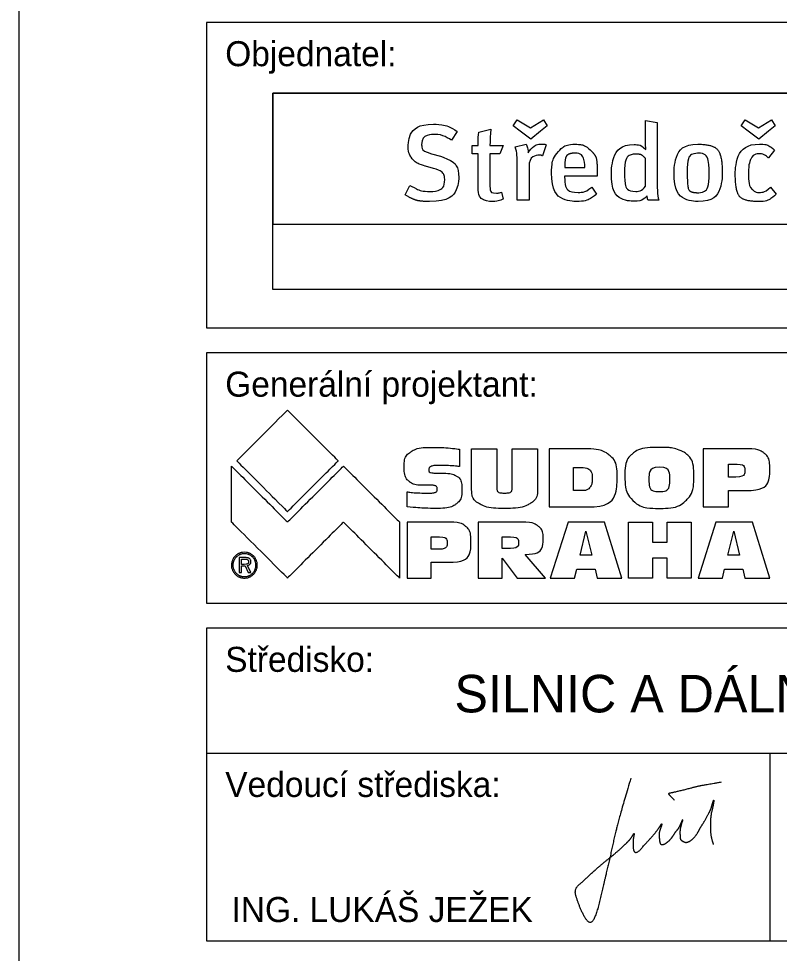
# Model space of a CAD drawing. Extents: x 2039 to 2249, y 760 to 1057.
# Drawn here: x 2038.7 to 2099.4, y 833.4 to 908.2 of the extents above; entities that cross this region are included whole.
import ezdxf

# ---------------------------------------------------------------- set-up
doc = ezdxf.new("R2010")
doc.units = 0
doc.layers.add('102_ZPEVNENI', color=7, linetype='Continuous')
doc.layers.add('120_ZPEVNENI', color=7, linetype='Continuous')

msp = doc.modelspace()

# ---------------------------------------------------------------- linework, layer by layer
at = {"layer": '102_ZPEVNENI'}
for points in [[(2083.73, 873.782), (2081.043, 873.782), (2081.043, 869.128), (2084.09, 869.128)], [(2096.82, 873.782), (2093.326, 873.782), (2093.326, 869.128), (2095.345, 869.128), (2095.345, 870.436), (2096.74, 870.436)], [(2083.563, 870.432), (2082.971, 870.432), (2082.971, 872.286), (2083.498, 872.286)], [(2095.943, 871.522), (2095.345, 871.522), (2095.345, 872.551), (2096.044, 872.551)], [(2073.025, 867.92), (2069.678, 867.92), (2069.678, 863.446), (2071.612, 863.446), (2071.612, 864.703), (2072.949, 864.703)], [(2078.766, 867.92), (2075.36, 867.92), (2075.36, 863.446), (2077.286, 863.446), (2077.286, 865.031), (2078.472, 863.446), (2080.73, 863.446), (2079.105, 865.333)], [(2083.063, 863.446), (2083.232, 864.143), (2084.695, 864.143), (2084.857, 863.446), (2086.838, 863.446), (2085.457, 867.92), (2082.546, 867.92), (2081.11, 863.446), (2083.063, 863.446)], [(2094.876, 863.446), (2095.045, 864.143), (2096.508, 864.143), (2096.67, 863.446), (2098.65, 863.446), (2097.27, 867.92), (2094.358, 867.92), (2092.923, 863.446), (2094.876, 863.446)], [(2072.185, 865.748), (2071.612, 865.748), (2071.612, 866.737), (2072.282, 866.737)], [(2077.929, 865.821), (2077.286, 865.821), (2077.286, 866.737), (2077.953, 866.737)], [(2083.97, 867.204), (2084.436, 865.28), (2083.498, 865.28), (2083.97, 867.204)], [(2095.783, 867.204), (2096.249, 865.28), (2095.31, 865.28), (2095.783, 867.204)], [(2056.709, 865.084), (2056.275, 865.084), (2056.275, 863.899), (2056.453, 863.899), (2056.453, 864.42), (2056.73, 864.42), (2056.98, 863.899), (2057.184, 863.899), (2056.92, 864.445)], [(2056.675, 864.538), (2056.453, 864.538), (2056.453, 864.963), (2056.675, 864.963)]]:
    msp.add_lwpolyline(points, dxfattribs=at)
for points in [[(2056.07, 872.814), (2056.07, 872.814), (2060.125, 876.869), (2060.125, 876.869), (2060.125, 876.869), (2060.125, 876.869), (2064.18, 872.814), (2064.18, 872.814), (2064.18, 872.814), (2064.18, 872.814), (2060.125, 868.759), (2060.125, 868.759), (2060.125, 868.759), (2060.125, 868.759), (2056.07, 872.814), (2056.07, 872.814)], [(2069.678, 869.147), (2070.405, 869.06), (2071.168, 869.016), (2071.968, 869.016), (2071.968, 869.016), (2072.733, 869.016), (2073.272, 869.129), (2073.584, 869.354), (2073.584, 869.354), (2073.899, 869.579), (2074.056, 869.967), (2074.056, 870.519), (2074.056, 870.519), (2074.056, 871.058), (2073.915, 871.418), (2073.631, 871.598), (2073.631, 871.598), (2073.365, 871.759), (2072.824, 871.84), (2072.007, 871.84), (2072.007, 871.84), (2071.616, 871.84), (2071.421, 871.932), (2071.421, 872.117), (2071.421, 872.117), (2071.421, 872.234), (2071.478, 872.319), (2071.593, 872.372), (2071.593, 872.372), (2071.711, 872.425), (2071.916, 872.451), (2072.209, 872.451), (2072.209, 872.451), (2072.706, 872.451), (2073.251, 872.423), (2073.87, 872.366), (2073.87, 872.366), (2073.87, 872.366), (2073.87, 873.738), (2073.87, 873.738), (2073.87, 873.738), (2073.131, 873.842), (2072.439, 873.894), (2071.77, 873.894), (2071.77, 873.894), (2070.927, 873.894), (2070.329, 873.774), (2069.977, 873.534), (2069.977, 873.534), (2069.624, 873.296), (2069.447, 872.916), (2069.447, 872.394), (2069.447, 872.394), (2069.447, 871.815), (2069.573, 871.413), (2069.825, 871.191), (2069.825, 871.191), (2070.08, 870.968), (2070.502, 870.858), (2071.093, 870.863), (2071.093, 870.863), (2071.093, 870.863), (2071.586, 870.863), (2071.586, 870.863), (2071.586, 870.863), (2071.759, 870.863), (2071.885, 870.844), (2071.964, 870.806), (2071.964, 870.806), (2072.043, 870.767), (2072.083, 870.684), (2072.083, 870.557), (2072.083, 870.557), (2072.083, 870.424), (2072.031, 870.337), (2071.928, 870.299), (2071.928, 870.299), (2071.827, 870.261), (2071.657, 870.242), (2071.417, 870.242), (2071.417, 870.242), (2070.673, 870.242), (2070.093, 870.275), (2069.678, 870.341), (2069.678, 870.341), (2069.678, 870.341), (2069.678, 869.147), (2069.678, 869.147)], [(2074.824, 870.617), (2074.824, 870.046), (2075.033, 869.635), (2075.452, 869.386), (2075.452, 869.386), (2075.871, 869.14), (2076.535, 869.016), (2077.444, 869.016), (2077.444, 869.016), (2078.391, 869.016), (2079.07, 869.14), (2079.482, 869.386), (2079.482, 869.386), (2079.896, 869.633), (2080.103, 870.05), (2080.103, 870.637), (2080.103, 870.637), (2080.103, 870.637), (2080.103, 873.782), (2080.103, 873.782), (2080.103, 873.782), (2080.103, 873.782), (2078.079, 873.782), (2078.079, 873.782), (2078.079, 873.782), (2078.079, 873.782), (2078.079, 870.7), (2078.079, 870.7), (2078.079, 870.7), (2078.079, 870.396), (2077.877, 870.244), (2077.472, 870.244), (2077.472, 870.244), (2077.056, 870.244), (2076.848, 870.401), (2076.848, 870.713), (2076.848, 870.713), (2076.848, 870.713), (2076.848, 873.782), (2076.848, 873.782), (2076.848, 873.782), (2076.848, 873.782), (2074.824, 873.782), (2074.824, 873.782), (2074.824, 873.782), (2074.824, 873.782), (2074.824, 870.617), (2074.824, 870.617)], [(2084.09, 869.128), (2085.668, 869.128), (2086.457, 869.952), (2086.457, 871.599), (2086.457, 871.599), (2086.457, 872.37), (2086.249, 872.926), (2085.833, 873.267), (2085.833, 873.267), (2085.416, 873.61), (2084.716, 873.782), (2083.73, 873.782)], [(2091.57, 873.62), (2091.154, 873.802), (2090.583, 873.894), (2089.855, 873.894), (2089.855, 873.894), (2088.836, 873.894), (2088.12, 873.726), (2087.705, 873.391), (2087.705, 873.391), (2087.291, 873.057), (2087.084, 872.463), (2087.084, 871.608), (2087.084, 871.608), (2087.084, 870.716), (2087.295, 870.061), (2087.716, 869.643)], [(2087.716, 869.643), (2088.138, 869.225), (2088.844, 869.016), (2089.834, 869.016), (2089.834, 869.016), (2090.785, 869.016), (2091.481, 869.217), (2091.922, 869.618), (2091.922, 869.618), (2092.365, 870.019), (2092.587, 870.682), (2092.587, 871.608), (2092.587, 871.608), (2092.587, 872.44), (2092.382, 873.029), (2091.973, 873.375), (2091.973, 873.375), (2091.861, 873.469), (2091.726, 873.551), (2091.57, 873.62)], [(2096.74, 870.436), (2098.013, 870.436), (2098.65, 871.006), (2098.65, 872.148), (2098.65, 872.148), (2098.65, 872.76), (2098.504, 873.185), (2098.212, 873.424), (2098.212, 873.424), (2097.922, 873.662), (2097.458, 873.782), (2096.82, 873.782)], [(2055.65, 867.92), (2055.65, 867.92), (2060.125, 863.446), (2060.125, 863.446), (2060.125, 863.446), (2060.125, 863.446), (2064.599, 867.92), (2064.599, 867.92), (2064.599, 867.92), (2064.599, 867.92), (2069.074, 863.446), (2069.074, 863.446), (2069.074, 863.446), (2069.074, 863.446), (2069.074, 867.92), (2069.074, 867.92), (2069.074, 867.92), (2069.074, 867.92), (2064.599, 872.395), (2064.599, 872.395), (2064.599, 872.395), (2064.599, 872.395), (2060.125, 867.92), (2060.125, 867.92), (2060.125, 867.92), (2060.125, 867.92), (2055.65, 872.395), (2055.65, 872.395), (2055.65, 872.395), (2055.65, 872.395), (2055.65, 867.92), (2055.65, 867.92)], [(2083.498, 872.286), (2083.892, 872.286), (2084.153, 872.22), (2084.279, 872.088), (2084.279, 872.088), (2084.404, 871.958), (2084.467, 871.736), (2084.467, 871.423), (2084.467, 871.423), (2084.467, 871.084), (2084.402, 870.834), (2084.271, 870.672), (2084.271, 870.672), (2084.143, 870.512), (2083.907, 870.432), (2083.563, 870.432)], [(2089.841, 872.308), (2090.392, 872.308), (2090.668, 871.999), (2090.668, 871.382), (2090.668, 871.382), (2090.668, 870.703), (2090.392, 870.363), (2089.841, 870.363), (2089.841, 870.363), (2089.282, 870.363), (2089.003, 870.687), (2089.003, 871.334), (2089.003, 871.334), (2089.003, 871.984), (2089.282, 872.308), (2089.841, 872.308)], [(2096.044, 872.551), (2096.457, 872.551), (2096.664, 872.383), (2096.664, 872.046), (2096.664, 872.046), (2096.664, 871.697), (2096.424, 871.522), (2095.943, 871.522)], [(2072.949, 864.703), (2074.169, 864.703), (2074.779, 865.252), (2074.779, 866.35), (2074.779, 866.35), (2074.779, 866.938), (2074.639, 867.347), (2074.359, 867.576), (2074.359, 867.576), (2074.081, 867.805), (2073.636, 867.92), (2073.025, 867.92)], [(2079.105, 865.333), (2080.068, 865.333), (2080.55, 865.754), (2080.55, 866.596), (2080.55, 866.596), (2080.55, 867.057), (2080.414, 867.393), (2080.142, 867.604), (2080.142, 867.604), (2079.87, 867.815), (2079.411, 867.92), (2078.766, 867.92)], [(2087.374, 863.446), (2087.374, 863.446), (2089.296, 863.446), (2089.296, 863.446), (2089.296, 863.446), (2089.296, 863.446), (2089.296, 865.028), (2089.296, 865.028), (2089.296, 865.028), (2089.296, 865.028), (2090.465, 865.028), (2090.465, 865.028), (2090.465, 865.028), (2090.465, 865.028), (2090.465, 863.446), (2090.465, 863.446), (2090.465, 863.446), (2090.465, 863.446), (2092.386, 863.446), (2092.386, 863.446), (2092.386, 863.446), (2092.386, 863.446), (2092.386, 867.92), (2092.386, 867.92), (2092.386, 867.92), (2092.386, 867.92), (2090.465, 867.92), (2090.465, 867.92), (2090.465, 867.92), (2090.465, 867.92), (2090.465, 866.328), (2090.465, 866.328), (2090.465, 866.328), (2090.465, 866.328), (2089.296, 866.328), (2089.296, 866.328), (2089.296, 866.328), (2089.296, 866.328), (2089.296, 867.92), (2089.296, 867.92), (2089.296, 867.92), (2089.296, 867.92), (2087.374, 867.92), (2087.374, 867.92), (2087.374, 867.92), (2087.374, 867.92), (2087.374, 863.446), (2087.374, 863.446)], [(2072.282, 866.737), (2072.678, 866.737), (2072.876, 866.575), (2072.876, 866.251), (2072.876, 866.251), (2072.876, 865.915), (2072.646, 865.748), (2072.185, 865.748)], [(2077.953, 866.737), (2078.38, 866.737), (2078.593, 866.597), (2078.593, 866.316), (2078.593, 866.316), (2078.593, 865.986), (2078.372, 865.821), (2077.929, 865.821)], [(2056.678, 865.504), (2056.539, 865.504), (2056.407, 865.479), (2056.284, 865.428), (2056.284, 865.428), (2056.161, 865.377), (2056.053, 865.304), (2055.958, 865.208), (2055.958, 865.208), (2055.859, 865.108), (2055.783, 864.994), (2055.73, 864.867), (2055.73, 864.867), (2055.677, 864.741), (2055.65, 864.61), (2055.65, 864.475), (2055.65, 864.475), (2055.65, 864.338), (2055.676, 864.208), (2055.728, 864.083), (2055.728, 864.083), (2055.779, 863.959), (2055.854, 863.848), (2055.953, 863.751), (2055.953, 863.751), (2056.05, 863.651), (2056.161, 863.576), (2056.285, 863.524), (2056.285, 863.524), (2056.342, 863.5), (2056.399, 863.482), (2056.458, 863.469)], [(2057.596, 864.471), (2057.596, 864.344), (2057.574, 864.227), (2057.53, 864.12), (2057.53, 864.12), (2057.485, 864.012), (2057.42, 863.916), (2057.335, 863.833), (2057.335, 863.833), (2057.244, 863.745), (2057.143, 863.678), (2057.03, 863.631), (2057.03, 863.631), (2056.917, 863.584), (2056.8, 863.561), (2056.678, 863.561), (2056.678, 863.561), (2056.557, 863.561), (2056.441, 863.584), (2056.331, 863.63), (2056.331, 863.63), (2056.22, 863.676), (2056.121, 863.743), (2056.033, 863.83), (2056.033, 863.83), (2055.945, 863.918), (2055.879, 864.017), (2055.832, 864.127), (2055.832, 864.127), (2055.786, 864.237), (2055.763, 864.353), (2055.763, 864.474), (2055.763, 864.474), (2055.763, 864.594), (2055.786, 864.71), (2055.834, 864.822), (2055.834, 864.822), (2055.881, 864.934), (2055.949, 865.035), (2056.038, 865.125), (2056.038, 865.125), (2056.124, 865.211), (2056.222, 865.277), (2056.331, 865.322), (2056.331, 865.322), (2056.441, 865.366), (2056.556, 865.389), (2056.678, 865.389), (2056.678, 865.389), (2056.803, 865.389), (2056.923, 865.366), (2057.034, 865.319), (2057.034, 865.319), (2057.147, 865.274), (2057.246, 865.207), (2057.335, 865.12), (2057.335, 865.12), (2057.419, 865.035), (2057.484, 864.937), (2057.529, 864.826), (2057.529, 864.826), (2057.574, 864.714), (2057.596, 864.596), (2057.596, 864.471)], [(2056.458, 863.469), (2056.529, 863.453), (2056.603, 863.446), (2056.678, 863.446), (2056.678, 863.446), (2056.814, 863.446), (2056.945, 863.472), (2057.072, 863.525), (2057.072, 863.525), (2057.199, 863.578), (2057.312, 863.654), (2057.412, 863.753), (2057.412, 863.753), (2057.509, 863.849), (2057.583, 863.958), (2057.633, 864.08), (2057.633, 864.08), (2057.684, 864.203), (2057.709, 864.335), (2057.709, 864.475), (2057.709, 864.475), (2057.709, 864.615), (2057.683, 864.747), (2057.632, 864.871), (2057.632, 864.871), (2057.581, 864.996), (2057.508, 865.107), (2057.412, 865.202), (2057.412, 865.202), (2057.315, 865.3), (2057.205, 865.375), (2057.079, 865.427), (2057.079, 865.427), (2056.954, 865.478), (2056.82, 865.504), (2056.678, 865.504)], [(2056.675, 864.963), (2056.795, 864.963), (2056.882, 864.946), (2056.935, 864.912), (2056.935, 864.912), (2056.988, 864.878), (2057.015, 864.822), (2057.015, 864.744), (2057.015, 864.744), (2057.015, 864.67), (2056.99, 864.616), (2056.939, 864.585), (2056.939, 864.585), (2056.889, 864.554), (2056.801, 864.538), (2056.675, 864.538)], [(2056.92, 864.445), (2057.005, 864.457), (2057.073, 864.491), (2057.124, 864.548), (2057.124, 864.548), (2057.174, 864.604), (2057.199, 864.673), (2057.199, 864.757), (2057.199, 864.757), (2057.199, 864.868), (2057.16, 864.951), (2057.079, 865.004), (2057.079, 865.004), (2056.999, 865.057), (2056.875, 865.084), (2056.709, 865.084)]]:
    msp.add_open_spline(points, degree=3, dxfattribs=at)
at = {"layer": '120_ZPEVNENI'}
for p, q in [((2233.65, 907.867), (2053.65, 907.867)), ((2053.65, 907.867), (2053.65, 883.446)), ((2073.671, 899.155), (2073.223, 898.456)), ((2075.405, 899.103), (2076.379, 899.336)), ((2078.317, 897.913), (2079.19, 898.136)), ((2080.802, 898.077), (2080.509, 897.196)), ((2099.032, 897.662), (2098.557, 897.032)), ((2071.635, 897.368), (2072.343, 897.161)), ((2088.727, 894.771), (2088.727, 896.99)), ((2071.799, 896.186), (2071.161, 896.367)), ((2082.273, 896.281), (2083.888, 896.281)), ((2069.522, 894.08), (2069.9, 894.84)), ((2084.429, 894.702), (2084.802, 894.124)), ((2098.704, 894.702), (2099.153, 894.124)), ((2077.234, 894.305), (2077.354, 893.735)), ((2089.804, 893.658), (2088.934, 893.658)), ((2053.65, 883.446), (2233.65, 883.446)), ((2053.65, 849.446), (2233.65, 849.446)), ((2098.65, 849.446), (2098.65, 834.446))]:
    msp.add_line(p, q, dxfattribs=at)
for points in [[(2038.65, 759.931), (2248.65, 759.931), (2248.65, 1056.931), (2038.65, 1056.931)], [(2058.95, 902.209), (2147.871, 902.209), (2147.871, 886.517), (2058.95, 886.517)], [(2053.65, 861.446), (2233.65, 861.446), (2233.65, 881.446), (2053.65, 881.446)], [(2053.65, 834.446), (2233.65, 834.446), (2233.65, 859.446), (2053.65, 859.446)]]:
    msp.add_lwpolyline(points, close=True, dxfattribs=at)
for points in [[(2137.41, 891.748), (2147.871, 902.209), (2058.95, 902.209), (2058.95, 891.748), (2137.41, 891.748)], [(2080.328, 899.163), (2079.553, 898.543), (2078.722, 899.172), (2078.152, 899.604), (2078.463, 900.069), (2079.541, 899.441), (2080.579, 900.069), (2080.862, 899.604), (2080.328, 899.163)], [(2088.727, 898.422), (2088.727, 900.019), (2089.666, 899.871), (2089.666, 895.176)], [(2098.548, 899.163), (2097.772, 898.543), (2096.942, 899.172), (2096.373, 899.604), (2096.684, 900.069), (2097.762, 899.441), (2098.798, 900.069), (2099.083, 899.604), (2098.548, 899.163)], [(2075.362, 894.667), (2075.362, 897.368), (2074.878, 897.368), (2074.878, 898.024), (2075.362, 898.024)], [(2076.303, 898.024), (2077.346, 898.024), (2077.096, 897.368), (2076.293, 897.368), (2076.293, 894.917)], [(2079.423, 896.609), (2079.423, 893.658), (2078.472, 893.658), (2078.472, 896.738)], [(2084.871, 895.781), (2084.871, 895.582), (2082.264, 895.582), (2082.264, 895.513)]]:
    msp.add_lwpolyline(points, dxfattribs=at)
for points, degree in [([(2069.754, 897.955), (2069.754, 897.955), (2069.754, 899.008), (2070.582, 899.725), (2071.782, 899.725)], 3), ([(2071.782, 899.725), (2071.782, 899.725), (2072.463, 899.725), (2073.145, 899.526), (2073.671, 899.155)], 3), ([(2071.818, 898.913), (2071.818, 898.913), (2071.23, 898.913), (2070.841, 898.594), (2070.841, 898.102)], 3), ([(2073.223, 898.456), (2073.223, 898.456), (2072.671, 898.785), (2072.292, 898.913), (2071.818, 898.913)], 3), ([(2075.362, 898.024), (2075.362, 898.024), (2075.362, 898.395), (2075.362, 898.776), (2075.405, 899.103)], 3), ([(2076.379, 899.336), (2076.379, 899.336), (2076.337, 898.983), (2076.303, 898.456), (2076.303, 898.024)], 3), ([(2079.19, 898.136), (2079.19, 898.136), (2079.292, 897.939), (2079.352, 897.688), (2079.352, 897.447)], 3), ([(2079.352, 897.447), (2079.352, 897.447), (2079.697, 897.921), (2080.043, 898.146), (2080.466, 898.146)], 3), ([(2080.466, 898.146), (2080.466, 898.146), (2080.604, 898.146), (2080.691, 898.129), (2080.802, 898.077)], 3), ([(2081.764, 897.542), (2081.764, 897.542), (2082.118, 897.947), (2082.55, 898.129), (2083.102, 898.129)], 3), ([(2083.102, 898.129), (2083.102, 898.129), (2083.533, 898.129), (2083.931, 898.016), (2084.302, 897.68)], 3), ([(2088.752, 897.705), (2088.752, 897.705), (2088.752, 897.705), (2088.727, 898.042), (2088.727, 898.422)], 3), ([(2091.005, 895.833), (2091.005, 895.833), (2091.005, 897.231), (2091.756, 898.129), (2092.913, 898.129)], 3), ([(2092.913, 898.129), (2094.156, 898.129), (2094.863, 897.205), (2094.863, 895.824)], 2), ([(2095.899, 895.788), (2095.899, 895.788), (2095.899, 897.376), (2096.848, 898.136), (2097.823, 898.136)], 3), ([(2097.823, 898.136), (2097.823, 898.136), (2098.297, 898.136), (2098.643, 898.024), (2099.032, 897.662)], 3), ([(2070.004, 897.084), (2070.004, 897.084), (2069.84, 897.325), (2069.754, 897.61), (2069.754, 897.955)], 3), ([(2070.841, 898.102), (2070.841, 898.102), (2070.841, 897.732), (2071.047, 897.542), (2071.635, 897.368)], 3), ([(2078.472, 896.738), (2078.472, 896.738), (2078.472, 897.291), (2078.413, 897.645), (2078.317, 897.913)], 3), ([(2081.221, 895.833), (2081.221, 895.833), (2081.221, 896.601), (2081.383, 897.11), (2081.764, 897.542)], 3), ([(2083.102, 897.412), (2082.569, 897.412), (2082.273, 896.99), (2082.273, 896.281)], 2), ([(2083.888, 896.281), (2083.888, 896.281), (2083.888, 896.99), (2083.576, 897.412), (2083.102, 897.412)], 3), ([(2084.302, 897.68), (2084.681, 897.334), (2084.871, 896.799), (2084.871, 895.781)], 2), ([(2085.999, 895.798), (2085.999, 895.798), (2085.999, 897.17), (2086.759, 898.102), (2087.811, 898.102)], 3), ([(2087.811, 898.102), (2087.811, 898.102), (2088.181, 898.102), (2088.484, 897.982), (2088.752, 897.705)], 3), ([(2092.921, 897.412), (2092.921, 897.412), (2092.318, 897.412), (2092.057, 896.954), (2092.057, 895.893)], 3), ([(2093.817, 895.806), (2093.817, 895.806), (2093.817, 897.041), (2093.473, 897.412), (2092.921, 897.412)], 3), ([(2071.161, 896.367), (2071.161, 896.367), (2070.617, 896.522), (2070.229, 896.747), (2070.004, 897.084)], 3), ([(2072.343, 897.161), (2072.343, 897.161), (2073.206, 896.911), (2073.809, 896.359), (2073.809, 895.461)], 3), ([(2080.241, 897.256), (2080.241, 897.256), (2079.844, 897.256), (2079.508, 896.963), (2079.423, 896.609)], 3), ([(2080.509, 897.196), (2080.415, 897.231), (2080.345, 897.256), (2080.241, 897.256)], 2), ([(2087.933, 897.342), (2087.933, 897.342), (2087.328, 897.342), (2087.05, 896.859), (2087.05, 895.806)], 3), ([(2088.727, 896.99), (2088.511, 897.222), (2088.251, 897.342), (2087.933, 897.342)], 2), ([(2097.133, 896.928), (2097.133, 896.928), (2097.002, 896.661), (2096.953, 896.255), (2096.953, 895.712)], 3), ([(2097.823, 897.368), (2097.823, 897.368), (2097.521, 897.368), (2097.27, 897.212), (2097.133, 896.928)], 3), ([(2098.557, 897.032), (2098.557, 897.032), (2098.297, 897.265), (2098.074, 897.368), (2097.823, 897.368)], 3), ([(2072.688, 895.297), (2072.688, 895.297), (2072.688, 895.738), (2072.411, 896.014), (2071.799, 896.186)], 3), ([(2092.057, 895.893), (2092.057, 894.624), (2092.378, 894.253), (2092.947, 894.253)], 2), ([(2073.809, 895.461), (2073.809, 895.461), (2073.809, 894.468), (2073.007, 893.546), (2071.48, 893.546)], 3), ([(2071.512, 894.348), (2071.512, 894.348), (2072.248, 894.348), (2072.688, 894.702), (2072.688, 895.297)], 3), ([(2083.232, 893.546), (2083.232, 893.546), (2081.997, 893.546), (2081.221, 894.434), (2081.221, 895.833)], 3), ([(2082.264, 895.513), (2082.264, 895.513), (2082.264, 894.909), (2082.49, 894.271), (2083.344, 894.271)], 3), ([(2087.786, 893.563), (2087.786, 893.563), (2086.672, 893.563), (2085.999, 894.434), (2085.999, 895.798)], 3), ([(2087.05, 895.806), (2087.05, 895.806), (2087.05, 894.84), (2087.242, 894.356), (2087.958, 894.356)], 3), ([(2089.666, 895.176), (2089.666, 895.176), (2089.666, 894.313), (2089.72, 893.873), (2089.804, 893.658)], 3), ([(2092.929, 893.546), (2092.929, 893.546), (2091.747, 893.546), (2091.005, 894.434), (2091.005, 895.833)], 3), ([(2094.863, 895.824), (2094.863, 895.824), (2094.863, 894.417), (2094.111, 893.546), (2092.929, 893.546)], 3), ([(2092.947, 894.253), (2092.947, 894.253), (2093.508, 894.253), (2093.817, 894.711), (2093.817, 895.806)], 3), ([(2097.755, 893.546), (2096.563, 893.546), (2095.899, 894.383), (2095.899, 895.788)], 2), ([(2096.953, 895.712), (2096.953, 895.712), (2096.953, 895.116), (2097.046, 894.737), (2097.245, 894.521)], 3), ([(2069.9, 894.84), (2069.9, 894.84), (2070.435, 894.529), (2070.91, 894.348), (2071.512, 894.348)], 3), ([(2076.501, 893.546), (2076.501, 893.546), (2075.655, 893.546), (2075.362, 894.047), (2075.362, 894.667)], 3), ([(2076.293, 894.917), (2076.293, 894.917), (2076.293, 894.374), (2076.414, 894.219), (2076.828, 894.219)], 3), ([(2083.344, 894.271), (2083.344, 894.271), (2083.748, 894.271), (2084.103, 894.417), (2084.429, 894.702)], 3), ([(2087.958, 894.356), (2087.958, 894.356), (2088.311, 894.356), (2088.598, 894.555), (2088.727, 894.771)], 3), ([(2097.245, 894.521), (2097.245, 894.521), (2097.383, 894.365), (2097.59, 894.271), (2097.823, 894.271)], 3), ([(2097.823, 894.271), (2097.823, 894.271), (2098.126, 894.271), (2098.42, 894.417), (2098.704, 894.702)], 3), ([(2071.48, 893.546), (2070.799, 893.546), (2070.108, 893.727), (2069.522, 894.08)], 2), ([(2077.354, 893.735), (2077.354, 893.735), (2077.069, 893.606), (2076.793, 893.546), (2076.501, 893.546)], 3), ([(2076.828, 894.219), (2076.828, 894.219), (2076.958, 894.219), (2077.069, 894.244), (2077.234, 894.305)], 3), ([(2084.802, 894.124), (2084.802, 894.124), (2084.345, 893.735), (2083.819, 893.546), (2083.232, 893.546)], 3), ([(2088.856, 893.994), (2088.856, 893.994), (2088.562, 893.702), (2088.217, 893.563), (2087.786, 893.563)], 3), ([(2088.934, 893.658), (2088.889, 893.752), (2088.882, 893.813), (2088.856, 893.994)], 2), ([(2099.153, 894.124), (2099.153, 894.124), (2098.754, 893.727), (2098.341, 893.546), (2097.755, 893.546)], 3), ([(2142.641, 886.517), (2142.641, 886.517), (2137.41, 891.748), (2137.41, 891.748), (2137.41, 891.748), (2137.41, 891.748), (2058.95, 891.748), (2058.95, 891.748), (2058.95, 891.748), (2058.95, 891.748), (2058.95, 886.517), (2058.95, 886.517), (2058.95, 886.517), (2058.95, 886.517), (2142.641, 886.517), (2142.641, 886.517)], 3), ([(2087.555, 847.436), (2087.126, 846.021), (2086.599, 844.163), (2086.297, 842.974), (2086.064, 841.93), (2085.808, 840.759), (2085.558, 839.73), (2085.324, 838.701), (2085.127, 837.846), (2084.849, 836.768), (2084.55, 836.032), (2084.264, 835.858), (2083.982, 836.138), (2083.666, 836.711), (2083.429, 837.274), (2083.24, 837.809), (2083.085, 838.299), (2083.212, 838.775), (2083.644, 839.113), (2084.131, 839.58), (2084.989, 840.366), (2086.193, 841.344), (2086.787, 841.849), (2087.2, 842.249), (2087.567, 842.63), (2087.863, 843.147), (2087.741, 842.594), (2087.724, 842.093), (2087.765, 841.69), (2087.903, 841.464), (2088.252, 841.626), (2088.483, 841.937), (2088.849, 842.334), (2089.376, 842.912), (2089.781, 843.436), (2090.08, 843.907), (2089.964, 843.51), (2089.842, 843.206), (2089.811, 842.954), (2089.839, 842.488), (2089.885, 842.241), (2089.97, 842.137), (2090.187, 842.15), (2090.399, 842.272), (2090.711, 842.525), (2090.97, 842.884), (2091.169, 843.209), (2091.384, 843.427), (2091.618, 843.948), (2091.732, 844.211), (2091.55, 843.645), (2091.478, 843.259), (2091.48, 842.962), (2091.5, 842.636), (2091.523, 842.512), (2091.977, 842.244), (2092.49, 842.54), (2092.881, 843.032), (2093.089, 843.466), (2093.432, 843.986), (2093.795, 844.68), (2093.95, 844.954), (2094.066, 845.367), (2094.209, 845.829), (2094.124, 845.184), (2093.93, 844.481), (2093.909, 843.579), (2093.91, 843.064), (2094.08, 842.309), (2094.153, 842.142)], 2), ([(2091.053, 845.673), (2090.653, 846.086), (2090.534, 846.25), (2090.982, 846.324), (2091.92, 846.553), (2092.995, 846.837), (2093.753, 846.961), (2094.803, 847.15)], 2)]:
    msp.add_open_spline(points, degree=degree, dxfattribs=at)

# ---------------------------------------------------------------- texts
for s, height, p in [('Objednatel:', 2, (2055.15, 904.367)), ('Generální projektant:', 2, (2055.15, 877.946)), ('Středisko:', 2, (2055.15, 855.946)), ('SILNIC A DÁLNIC', 3, (2073.462, 852.705)), ('Vedoucí střediska:', 2, (2055.15, 845.946)), ('ING. LUKÁŠ JEŽEK', 2, (2055.65, 835.946))]:
    msp.add_text(s, height=height, dxfattribs=at).set_placement(p)

doc.saveas('drawing.dxf')
